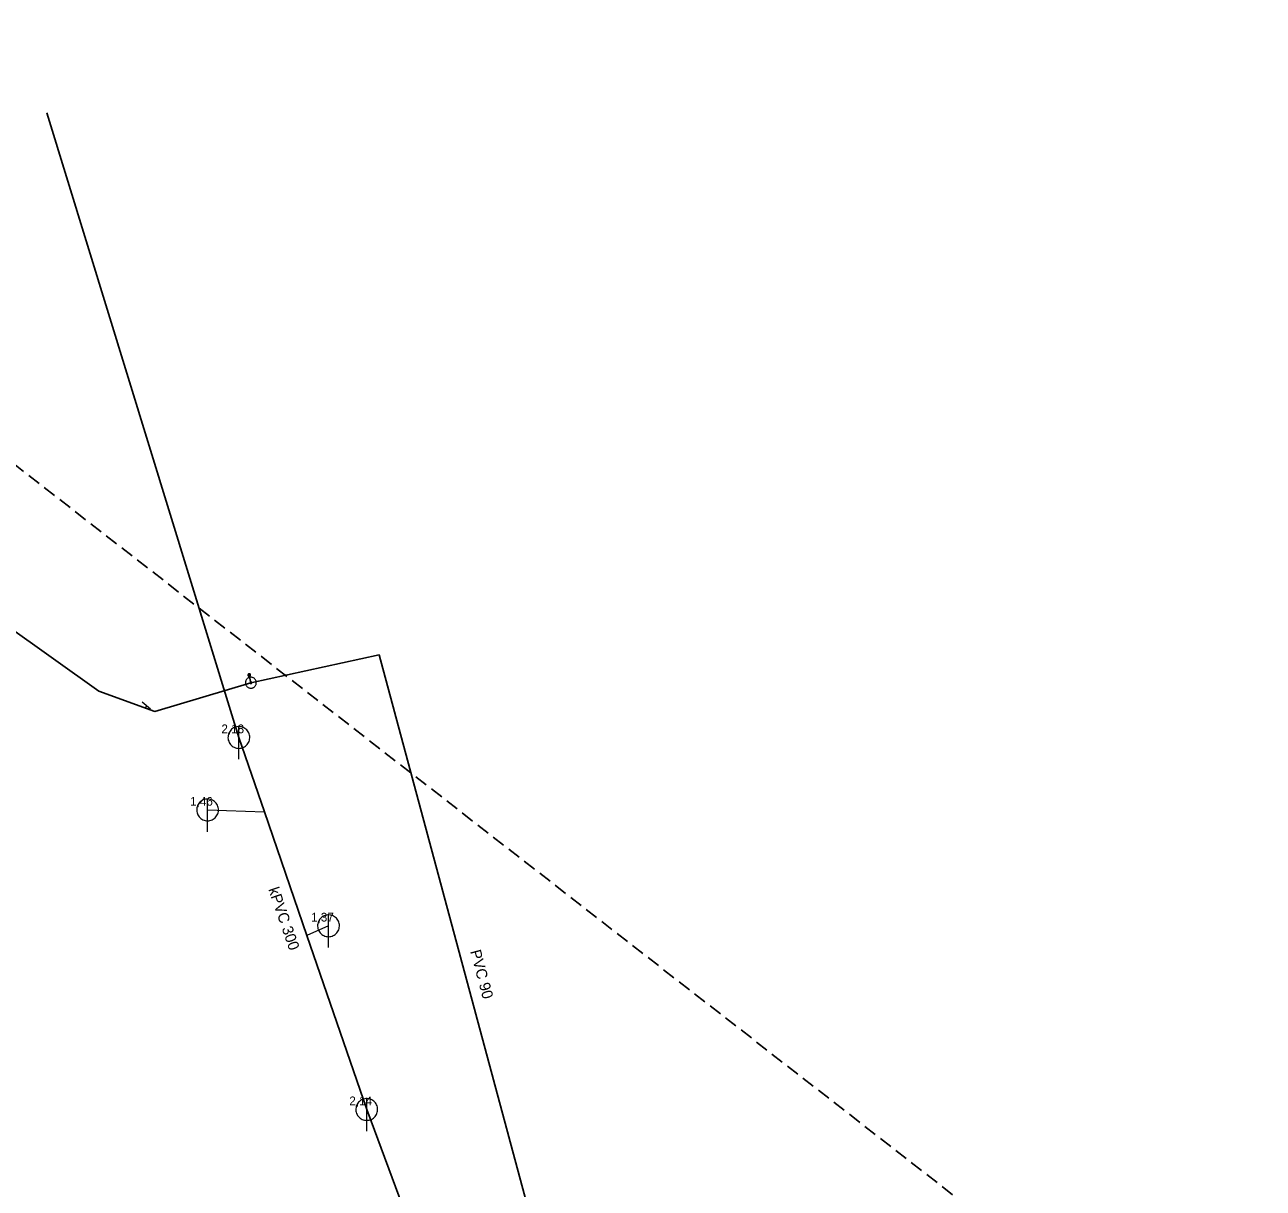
# Model space of a CAD drawing. Extents: x -683466 to -682479, y -996772 to -995963.
# Drawn here: x -682772.5 to -682658.8, y -996467.6 to -996360.9 of the extents above; entities that cross this region are included whole.
import ezdxf

# ---------------------------------------------------------------- set-up
doc = ezdxf.new("R2010")
doc.units = 0
doc.header["$LTSCALE"] = 0.4
doc.linetypes.add('MEDIUM_DASHED', pattern=[4.5, 3, -1.5])
doc.layers.add('1', color=7, linetype='Continuous')
for name, color, linetype, lineweight in [('11', 7, 'Continuous', 13), ('14', 7, 'Continuous', 25), ('17', 7, 'Continuous', 25), ('22', 7, 'Continuous', 13), ('34', 7, 'Continuous', 13), ('47', 7, 'Continuous', 13), ('63', 7, 'MEDIUM_DASHED', 25), ('9', 7, 'Continuous', 13)]:
    doc.layers.add(name, color=color, linetype=linetype, lineweight=lineweight)

msp = doc.modelspace()

# ---------------------------------------------------------------- linework, layer by layer
at = {"layer": '11'}
for p, q in [((-682755.69, -996432.879), (-682750.48, -996433.039)), ((-682744.596, -996443.508), (-682746.572, -996444.406))]:
    msp.add_line(p, q, dxfattribs=at)
at = {"layer": '14', "lineweight": 13}
msp.add_line((-682761.363, -996423.537), (-682761.309, -996423.309), dxfattribs=at)
at = {"layer": '14'}
msp.add_line((-682741.09, -996460.359), (-682726.26, -996500.32), dxfattribs=at)
for points in [[(-682770.44, -996368.94), (-682753.583, -996423.745), (-682752.82, -996426.23)], [(-682752.82, -996426.23), (-682750.48, -996433.039), (-682746.572, -996444.406), (-682741.09, -996460.359)]]:
    msp.add_lwpolyline(points, dxfattribs=at)
at = {"layer": '17'}
msp.add_line((-682751.718, -996421.207), (-682751.87, -996420.51), dxfattribs=at)
for points in [[(-682751.718, -996421.207), (-682760.52, -996423.84), (-682765.68, -996421.989), (-682774.19, -996415.899), (-682776.629, -996417.879), (-682778.359, -996420.489), (-682785.68, -996422.469), (-682789.414, -996420.431), (-682805.899, -996413.609)], [(-682688.579, -996470.29), (-682723.62, -996479.34), (-682739.951, -996418.663), (-682751.718, -996421.207)]]:
    msp.add_lwpolyline(points, dxfattribs=at)
at = {"layer": '22'}
for p, q in [((-682752.82, -996428.23), (-682752.819, -996425.23)), ((-682755.69, -996434.879), (-682755.689, -996431.879)), ((-682744.596, -996445.508), (-682744.595, -996442.508)), ((-682741.09, -996462.359), (-682741.089, -996459.359))]:
    msp.add_line(p, q, dxfattribs=at)
for points in [[(-682751.82, -996426.23), (-682751.825, -996426.121), (-682751.843, -996426.013), (-682751.873, -996425.907), (-682751.913, -996425.806), (-682751.965, -996425.709), (-682752.027, -996425.619), (-682752.099, -996425.536), (-682752.179, -996425.462), (-682752.267, -996425.396), (-682752.361, -996425.341), (-682752.461, -996425.296), (-682752.566, -996425.263), (-682752.673, -996425.241), (-682752.782, -996425.231), (-682752.892, -996425.233), (-682753, -996425.247), (-682753.107, -996425.272), (-682753.21, -996425.309), (-682753.308, -996425.358), (-682753.4, -996425.416), (-682753.486, -996425.485), (-682753.563, -996425.562), (-682753.632, -996425.648), (-682753.691, -996425.74), (-682753.739, -996425.838), (-682753.776, -996425.941), (-682753.802, -996426.048), (-682753.816, -996426.156), (-682753.819, -996426.266), (-682753.809, -996426.375), (-682753.788, -996426.482), (-682753.754, -996426.586), (-682753.71, -996426.686), (-682753.655, -996426.781), (-682753.589, -996426.869), (-682753.515, -996426.949), (-682753.432, -996427.021), (-682753.342, -996427.083), (-682753.246, -996427.135), (-682753.144, -996427.176), (-682753.039, -996427.206), (-682752.931, -996427.224), (-682752.821, -996427.23), (-682752.712, -996427.224), (-682752.604, -996427.206), (-682752.499, -996427.177), (-682752.397, -996427.136), (-682752.3, -996427.084), (-682752.21, -996427.022), (-682752.127, -996426.951), (-682752.052, -996426.871), (-682751.987, -996426.783), (-682751.931, -996426.689), (-682751.887, -996426.589), (-682751.853, -996426.485), (-682751.831, -996426.377), (-682751.821, -996426.268)], [(-682754.69, -996432.879), (-682754.695, -996432.77), (-682754.713, -996432.662), (-682754.743, -996432.556), (-682754.783, -996432.455), (-682754.835, -996432.358), (-682754.897, -996432.268), (-682754.969, -996432.185), (-682755.049, -996432.111), (-682755.137, -996432.045), (-682755.231, -996431.99), (-682755.331, -996431.945), (-682755.436, -996431.912), (-682755.543, -996431.89), (-682755.652, -996431.88), (-682755.762, -996431.882), (-682755.87, -996431.896), (-682755.977, -996431.921), (-682756.08, -996431.958), (-682756.178, -996432.007), (-682756.27, -996432.065), (-682756.356, -996432.134), (-682756.433, -996432.211), (-682756.502, -996432.297), (-682756.561, -996432.389), (-682756.609, -996432.487), (-682756.646, -996432.59), (-682756.672, -996432.697), (-682756.686, -996432.805), (-682756.689, -996432.915), (-682756.679, -996433.024), (-682756.658, -996433.131), (-682756.624, -996433.235), (-682756.58, -996433.335), (-682756.525, -996433.43), (-682756.459, -996433.518), (-682756.385, -996433.598), (-682756.302, -996433.67), (-682756.212, -996433.732), (-682756.116, -996433.784), (-682756.014, -996433.825), (-682755.909, -996433.855), (-682755.801, -996433.873), (-682755.691, -996433.879), (-682755.582, -996433.873), (-682755.474, -996433.855), (-682755.369, -996433.826), (-682755.267, -996433.785), (-682755.17, -996433.733), (-682755.08, -996433.671), (-682754.997, -996433.6), (-682754.922, -996433.52), (-682754.857, -996433.432), (-682754.801, -996433.338), (-682754.757, -996433.238), (-682754.723, -996433.134), (-682754.701, -996433.026), (-682754.691, -996432.917)], [(-682743.596, -996443.508), (-682743.601, -996443.399), (-682743.619, -996443.291), (-682743.649, -996443.185), (-682743.689, -996443.084), (-682743.741, -996442.987), (-682743.803, -996442.897), (-682743.875, -996442.814), (-682743.955, -996442.74), (-682744.043, -996442.674), (-682744.137, -996442.619), (-682744.237, -996442.574), (-682744.342, -996442.541), (-682744.449, -996442.519), (-682744.558, -996442.509), (-682744.668, -996442.511), (-682744.776, -996442.525), (-682744.883, -996442.55), (-682744.986, -996442.587), (-682745.084, -996442.636), (-682745.176, -996442.694), (-682745.262, -996442.763), (-682745.339, -996442.84), (-682745.408, -996442.926), (-682745.467, -996443.018), (-682745.515, -996443.116), (-682745.552, -996443.219), (-682745.578, -996443.326), (-682745.592, -996443.434), (-682745.595, -996443.544), (-682745.585, -996443.653), (-682745.564, -996443.76), (-682745.53, -996443.864), (-682745.486, -996443.964), (-682745.431, -996444.059), (-682745.365, -996444.147), (-682745.291, -996444.227), (-682745.208, -996444.299), (-682745.118, -996444.361), (-682745.022, -996444.413), (-682744.92, -996444.454), (-682744.815, -996444.484), (-682744.707, -996444.502), (-682744.597, -996444.508), (-682744.488, -996444.502), (-682744.38, -996444.484), (-682744.275, -996444.455), (-682744.173, -996444.414), (-682744.076, -996444.362), (-682743.986, -996444.3), (-682743.903, -996444.229), (-682743.828, -996444.149), (-682743.763, -996444.061), (-682743.707, -996443.967), (-682743.663, -996443.867), (-682743.629, -996443.763), (-682743.607, -996443.655), (-682743.597, -996443.546)], [(-682740.09, -996460.359), (-682740.095, -996460.25), (-682740.113, -996460.142), (-682740.143, -996460.036), (-682740.183, -996459.935), (-682740.235, -996459.838), (-682740.297, -996459.748), (-682740.369, -996459.665), (-682740.449, -996459.591), (-682740.537, -996459.525), (-682740.631, -996459.47), (-682740.731, -996459.425), (-682740.836, -996459.392), (-682740.943, -996459.37), (-682741.052, -996459.36), (-682741.162, -996459.362), (-682741.27, -996459.376), (-682741.377, -996459.401), (-682741.48, -996459.438), (-682741.578, -996459.487), (-682741.67, -996459.545), (-682741.756, -996459.614), (-682741.833, -996459.691), (-682741.902, -996459.777), (-682741.961, -996459.869), (-682742.009, -996459.967), (-682742.046, -996460.07), (-682742.072, -996460.177), (-682742.086, -996460.285), (-682742.089, -996460.395), (-682742.079, -996460.504), (-682742.058, -996460.611), (-682742.024, -996460.715), (-682741.98, -996460.815), (-682741.925, -996460.91), (-682741.859, -996460.998), (-682741.785, -996461.078), (-682741.702, -996461.15), (-682741.612, -996461.212), (-682741.516, -996461.264), (-682741.414, -996461.305), (-682741.309, -996461.335), (-682741.201, -996461.353), (-682741.091, -996461.359), (-682740.982, -996461.353), (-682740.874, -996461.335), (-682740.769, -996461.306), (-682740.667, -996461.265), (-682740.57, -996461.213), (-682740.48, -996461.151), (-682740.397, -996461.08), (-682740.322, -996461), (-682740.257, -996460.912), (-682740.201, -996460.818), (-682740.157, -996460.718), (-682740.123, -996460.614), (-682740.101, -996460.506), (-682740.091, -996460.397)]]:
    msp.add_lwpolyline(points, close=True, dxfattribs=at)
at = {"layer": '34'}
msp.add_line((-682760.926, -996423.631), (-682761.69, -996422.985), dxfattribs=at)
at = {"layer": '47'}
for points in [[(-682751.218, -996421.207), (-682751.221, -996421.155), (-682751.229, -996421.103), (-682751.243, -996421.053), (-682751.261, -996421.004), (-682751.285, -996420.957), (-682751.314, -996420.913), (-682751.347, -996420.873), (-682751.384, -996420.836), (-682751.424, -996420.803), (-682751.468, -996420.774), (-682751.515, -996420.75), (-682751.564, -996420.732), (-682751.614, -996420.718), (-682751.666, -996420.71), (-682751.718, -996420.707), (-682751.77, -996420.71), (-682751.822, -996420.718), (-682751.873, -996420.732), (-682751.921, -996420.75), (-682751.968, -996420.774), (-682752.012, -996420.803), (-682752.053, -996420.836), (-682752.09, -996420.873), (-682752.123, -996420.913), (-682752.151, -996420.957), (-682752.175, -996421.004), (-682752.194, -996421.053), (-682752.206, -996421.103), (-682752.215, -996421.155), (-682752.218, -996421.207), (-682752.215, -996421.259), (-682752.206, -996421.311), (-682752.194, -996421.362), (-682752.175, -996421.41), (-682752.151, -996421.457), (-682752.123, -996421.501), (-682752.09, -996421.542), (-682752.053, -996421.579), (-682752.012, -996421.612), (-682751.968, -996421.64), (-682751.921, -996421.664), (-682751.873, -996421.683), (-682751.822, -996421.696), (-682751.77, -996421.704), (-682751.718, -996421.707), (-682751.666, -996421.704), (-682751.614, -996421.696), (-682751.564, -996421.683), (-682751.515, -996421.664), (-682751.468, -996421.64), (-682751.424, -996421.612), (-682751.384, -996421.579), (-682751.347, -996421.542), (-682751.314, -996421.501), (-682751.285, -996421.457), (-682751.261, -996421.41), (-682751.243, -996421.362), (-682751.229, -996421.311), (-682751.221, -996421.259)], [(-682751.636, -996421.207), (-682751.636, -996421.198), (-682751.638, -996421.19), (-682751.64, -996421.182), (-682751.643, -996421.174), (-682751.647, -996421.166), (-682751.652, -996421.159), (-682751.657, -996421.152), (-682751.663, -996421.146), (-682751.67, -996421.141), (-682751.677, -996421.136), (-682751.684, -996421.132), (-682751.693, -996421.129), (-682751.701, -996421.127), (-682751.709, -996421.125), (-682751.718, -996421.125), (-682751.727, -996421.125), (-682751.735, -996421.127), (-682751.743, -996421.129), (-682751.751, -996421.132), (-682751.759, -996421.136), (-682751.766, -996421.141), (-682751.773, -996421.146), (-682751.779, -996421.152), (-682751.785, -996421.159), (-682751.789, -996421.166), (-682751.793, -996421.174), (-682751.796, -996421.182), (-682751.798, -996421.19), (-682751.8, -996421.198), (-682751.8, -996421.207), (-682751.8, -996421.216), (-682751.798, -996421.224), (-682751.796, -996421.232), (-682751.793, -996421.24), (-682751.789, -996421.248), (-682751.785, -996421.255), (-682751.779, -996421.262), (-682751.773, -996421.268), (-682751.766, -996421.274), (-682751.759, -996421.278), (-682751.751, -996421.282), (-682751.743, -996421.285), (-682751.735, -996421.287), (-682751.727, -996421.289), (-682751.718, -996421.289), (-682751.709, -996421.289), (-682751.701, -996421.287), (-682751.693, -996421.285), (-682751.684, -996421.282), (-682751.677, -996421.278), (-682751.67, -996421.274), (-682751.663, -996421.268), (-682751.657, -996421.262), (-682751.652, -996421.255), (-682751.647, -996421.248), (-682751.643, -996421.24), (-682751.64, -996421.232), (-682751.638, -996421.224), (-682751.636, -996421.216)]]:
    msp.add_lwpolyline(points, close=True, dxfattribs=at)
at = {"layer": '63'}
msp.add_lwpolyline([(-683425.281, -996021.839), (-683425.281, -996016.256), (-683425.281, -996016.256), (-683335.962, -995963.223), (-683335.962, -995963.223), (-682479.059, -996630.324), (-682479.059, -996630.324), (-682551.631, -996711.269), (-682551.631, -996711.269), (-683416.907, -996083.246), (-683416.907, -996083.246)], close=True, dxfattribs=at)
at = {"layer": '9'}
for points in [[(-682751.996, -996420.51), (-682751.996, -996420.523), (-682751.994, -996420.536), (-682751.991, -996420.549), (-682751.986, -996420.561), (-682751.98, -996420.573), (-682751.973, -996420.584), (-682751.965, -996420.594), (-682751.955, -996420.604), (-682751.945, -996420.612), (-682751.934, -996420.619), (-682751.922, -996420.625), (-682751.91, -996420.63), (-682751.897, -996420.633), (-682751.884, -996420.635), (-682751.871, -996420.637), (-682751.858, -996420.636), (-682751.845, -996420.634), (-682751.832, -996420.631), (-682751.82, -996420.626), (-682751.808, -996420.62), (-682751.797, -996420.613), (-682751.787, -996420.605), (-682751.777, -996420.595), (-682751.769, -996420.585), (-682751.762, -996420.574), (-682751.756, -996420.562), (-682751.751, -996420.55), (-682751.748, -996420.537), (-682751.746, -996420.524), (-682751.744, -996420.511), (-682751.745, -996420.498), (-682751.747, -996420.485), (-682751.75, -996420.472), (-682751.755, -996420.46), (-682751.761, -996420.448), (-682751.768, -996420.437), (-682751.776, -996420.427), (-682751.786, -996420.417), (-682751.796, -996420.409), (-682751.807, -996420.402), (-682751.819, -996420.396), (-682751.831, -996420.391), (-682751.844, -996420.388), (-682751.857, -996420.386), (-682751.87, -996420.385), (-682751.883, -996420.385), (-682751.896, -996420.387), (-682751.909, -996420.39), (-682751.921, -996420.395), (-682751.933, -996420.401), (-682751.944, -996420.408), (-682751.954, -996420.416), (-682751.964, -996420.426), (-682751.972, -996420.436), (-682751.979, -996420.447), (-682751.985, -996420.459), (-682751.99, -996420.471), (-682751.993, -996420.484), (-682751.995, -996420.497)], [(-682751.976, -996420.51), (-682751.977, -996420.521), (-682751.975, -996420.532), (-682751.972, -996420.543), (-682751.968, -996420.553), (-682751.963, -996420.563), (-682751.957, -996420.572), (-682751.95, -996420.581), (-682751.942, -996420.589), (-682751.933, -996420.596), (-682751.924, -996420.602), (-682751.914, -996420.607), (-682751.904, -996420.611), (-682751.893, -996420.614), (-682751.882, -996420.617), (-682751.871, -996420.617), (-682751.86, -996420.617), (-682751.849, -996420.615), (-682751.838, -996420.612), (-682751.828, -996420.608), (-682751.818, -996420.603), (-682751.809, -996420.597), (-682751.8, -996420.59), (-682751.792, -996420.582), (-682751.785, -996420.573), (-682751.779, -996420.564), (-682751.774, -996420.554), (-682751.77, -996420.544), (-682751.767, -996420.533), (-682751.765, -996420.522), (-682751.764, -996420.511), (-682751.764, -996420.5), (-682751.766, -996420.489), (-682751.769, -996420.478), (-682751.773, -996420.468), (-682751.778, -996420.458), (-682751.784, -996420.449), (-682751.791, -996420.44), (-682751.799, -996420.432), (-682751.808, -996420.425), (-682751.817, -996420.419), (-682751.827, -996420.414), (-682751.837, -996420.41), (-682751.848, -996420.407), (-682751.858, -996420.405), (-682751.87, -996420.405), (-682751.881, -996420.404), (-682751.892, -996420.406), (-682751.903, -996420.409), (-682751.913, -996420.413), (-682751.923, -996420.418), (-682751.932, -996420.424), (-682751.941, -996420.431), (-682751.949, -996420.439), (-682751.956, -996420.448), (-682751.962, -996420.457), (-682751.967, -996420.467), (-682751.971, -996420.477), (-682751.974, -996420.488), (-682751.976, -996420.499)], [(-682751.957, -996420.51), (-682751.957, -996420.519), (-682751.956, -996420.528), (-682751.953, -996420.537), (-682751.95, -996420.545), (-682751.946, -996420.553), (-682751.941, -996420.561), (-682751.934, -996420.568), (-682751.929, -996420.574), (-682751.922, -996420.58), (-682751.914, -996420.585), (-682751.906, -996420.589), (-682751.898, -996420.592), (-682751.889, -996420.595), (-682751.88, -996420.596), (-682751.871, -996420.598), (-682751.862, -996420.597), (-682751.853, -996420.596), (-682751.844, -996420.593), (-682751.836, -996420.59), (-682751.828, -996420.586), (-682751.82, -996420.581), (-682751.813, -996420.575), (-682751.807, -996420.569), (-682751.801, -996420.562), (-682751.796, -996420.554), (-682751.792, -996420.546), (-682751.789, -996420.538), (-682751.786, -996420.529), (-682751.785, -996420.52), (-682751.782, -996420.511), (-682751.784, -996420.502), (-682751.785, -996420.493), (-682751.788, -996420.484), (-682751.791, -996420.476), (-682751.795, -996420.468), (-682751.8, -996420.46), (-682751.806, -996420.453), (-682751.812, -996420.447), (-682751.819, -996420.441), (-682751.827, -996420.436), (-682751.835, -996420.432), (-682751.843, -996420.429), (-682751.852, -996420.426), (-682751.861, -996420.425), (-682751.87, -996420.424), (-682751.879, -996420.424), (-682751.888, -996420.425), (-682751.897, -996420.428), (-682751.905, -996420.431), (-682751.913, -996420.435), (-682751.921, -996420.44), (-682751.928, -996420.446), (-682751.934, -996420.452), (-682751.94, -996420.459), (-682751.945, -996420.467), (-682751.949, -996420.475), (-682751.952, -996420.483), (-682751.955, -996420.492), (-682751.956, -996420.501)], [(-682751.937, -996420.51), (-682751.937, -996420.517), (-682751.936, -996420.524), (-682751.934, -996420.531), (-682751.932, -996420.537), (-682751.929, -996420.543), (-682751.925, -996420.549), (-682751.921, -996420.555), (-682751.916, -996420.56), (-682751.91, -996420.564), (-682751.904, -996420.568), (-682751.898, -996420.571), (-682751.892, -996420.574), (-682751.885, -996420.575), (-682751.878, -996420.578), (-682751.871, -996420.578), (-682751.864, -996420.578), (-682751.857, -996420.576), (-682751.85, -996420.575), (-682751.844, -996420.572), (-682751.837, -996420.569), (-682751.832, -996420.565), (-682751.826, -996420.561), (-682751.821, -996420.556), (-682751.817, -996420.55), (-682751.813, -996420.544), (-682751.809, -996420.538), (-682751.807, -996420.532), (-682751.805, -996420.525), (-682751.804, -996420.518), (-682751.803, -996420.511), (-682751.803, -996420.504), (-682751.804, -996420.497), (-682751.806, -996420.49), (-682751.809, -996420.484), (-682751.812, -996420.477), (-682751.816, -996420.472), (-682751.82, -996420.466), (-682751.825, -996420.461), (-682751.831, -996420.457), (-682751.836, -996420.453), (-682751.843, -996420.45), (-682751.849, -996420.447), (-682751.856, -996420.445), (-682751.863, -996420.444), (-682751.87, -996420.444), (-682751.877, -996420.444), (-682751.884, -996420.444), (-682751.891, -996420.446), (-682751.897, -996420.449), (-682751.903, -996420.452), (-682751.909, -996420.456), (-682751.915, -996420.46), (-682751.92, -996420.465), (-682751.924, -996420.471), (-682751.928, -996420.476), (-682751.931, -996420.483), (-682751.934, -996420.489), (-682751.934, -996420.496), (-682751.937, -996420.503)], [(-682751.917, -996420.51), (-682751.917, -996420.515), (-682751.917, -996420.52), (-682751.916, -996420.525), (-682751.914, -996420.529), (-682751.912, -996420.534), (-682751.909, -996420.538), (-682751.906, -996420.541), (-682751.902, -996420.545), (-682751.899, -996420.548), (-682751.895, -996420.551), (-682751.89, -996420.553), (-682751.886, -996420.555), (-682751.881, -996420.556), (-682751.876, -996420.558), (-682751.871, -996420.558), (-682751.866, -996420.558), (-682751.861, -996420.557), (-682751.856, -996420.556), (-682751.852, -996420.554), (-682751.847, -996420.552), (-682751.843, -996420.549), (-682751.839, -996420.546), (-682751.836, -996420.542), (-682751.833, -996420.539), (-682751.83, -996420.535), (-682751.828, -996420.53), (-682751.826, -996420.526), (-682751.825, -996420.521), (-682751.824, -996420.516), (-682751.823, -996420.511), (-682751.823, -996420.506), (-682751.824, -996420.501), (-682751.825, -996420.496), (-682751.827, -996420.492), (-682751.829, -996420.487), (-682751.832, -996420.483), (-682751.835, -996420.479), (-682751.838, -996420.476), (-682751.842, -996420.473), (-682751.846, -996420.47), (-682751.851, -996420.468), (-682751.855, -996420.466), (-682751.86, -996420.465), (-682751.865, -996420.464), (-682751.87, -996420.464), (-682751.875, -996420.464), (-682751.88, -996420.465), (-682751.885, -996420.465), (-682751.889, -996420.467), (-682751.894, -996420.469), (-682751.898, -996420.472), (-682751.901, -996420.475), (-682751.905, -996420.478), (-682751.907, -996420.482), (-682751.911, -996420.486), (-682751.913, -996420.491), (-682751.915, -996420.495), (-682751.916, -996420.5), (-682751.917, -996420.505)], [(-682751.897, -996420.51), (-682751.897, -996420.513), (-682751.898, -996420.516), (-682751.897, -996420.518), (-682751.896, -996420.521), (-682751.895, -996420.524), (-682751.893, -996420.526), (-682751.891, -996420.528), (-682751.889, -996420.53), (-682751.887, -996420.532), (-682751.885, -996420.534), (-682751.882, -996420.536), (-682751.879, -996420.537), (-682751.877, -996420.537), (-682751.874, -996420.538), (-682751.871, -996420.538), (-682751.868, -996420.538), (-682751.865, -996420.538), (-682751.862, -996420.537), (-682751.86, -996420.536), (-682751.857, -996420.535), (-682751.855, -996420.533), (-682751.852, -996420.531), (-682751.85, -996420.529), (-682751.849, -996420.527), (-682751.847, -996420.525), (-682751.846, -996420.522), (-682751.844, -996420.519), (-682751.844, -996420.517), (-682751.843, -996420.514), (-682751.842, -996420.511), (-682751.843, -996420.508), (-682751.843, -996420.505), (-682751.844, -996420.502), (-682751.845, -996420.5), (-682751.846, -996420.497), (-682751.848, -996420.495), (-682751.849, -996420.492), (-682751.851, -996420.49), (-682751.854, -996420.489), (-682751.856, -996420.487), (-682751.858, -996420.486), (-682751.861, -996420.485), (-682751.864, -996420.484), (-682751.867, -996420.484), (-682751.87, -996420.483), (-682751.873, -996420.484), (-682751.876, -996420.483), (-682751.878, -996420.485), (-682751.881, -996420.485), (-682751.884, -996420.486), (-682751.886, -996420.488), (-682751.888, -996420.489), (-682751.89, -996420.491), (-682751.892, -996420.494), (-682751.894, -996420.496), (-682751.895, -996420.499), (-682751.896, -996420.501), (-682751.897, -996420.504), (-682751.897, -996420.507)], [(-682751.878, -996420.51), (-682751.878, -996420.512), (-682751.878, -996420.512), (-682751.877, -996420.512), (-682751.877, -996420.514), (-682751.878, -996420.515), (-682751.876, -996420.515), (-682751.876, -996420.515), (-682751.876, -996420.517), (-682751.876, -996420.517), (-682751.875, -996420.518), (-682751.873, -996420.518), (-682751.873, -996420.518), (-682751.873, -996420.519), (-682751.871, -996420.519), (-682751.871, -996420.519), (-682751.87, -996420.519), (-682751.869, -996420.519), (-682751.869, -996420.518), (-682751.868, -996420.518), (-682751.866, -996420.518), (-682751.866, -996420.517), (-682751.866, -996420.517), (-682751.865, -996420.516), (-682751.865, -996420.516), (-682751.863, -996420.515), (-682751.863, -996420.514), (-682751.862, -996420.513), (-682751.862, -996420.513), (-682751.862, -996420.512), (-682751.862, -996420.511), (-682751.862, -996420.51), (-682751.862, -996420.509), (-682751.862, -996420.509), (-682751.863, -996420.508), (-682751.863, -996420.507), (-682751.864, -996420.506), (-682751.864, -996420.506), (-682751.865, -996420.505), (-682751.865, -996420.505), (-682751.866, -996420.504), (-682751.867, -996420.504), (-682751.868, -996420.503), (-682751.868, -996420.503), (-682751.869, -996420.503), (-682751.87, -996420.503), (-682751.871, -996420.503), (-682751.872, -996420.503), (-682751.872, -996420.503), (-682751.873, -996420.504), (-682751.874, -996420.503), (-682751.875, -996420.505), (-682751.875, -996420.505), (-682751.876, -996420.505), (-682751.876, -996420.505), (-682751.877, -996420.507), (-682751.877, -996420.508), (-682751.877, -996420.509), (-682751.878, -996420.509), (-682751.878, -996420.51)]]:
    msp.add_lwpolyline(points, close=True, dxfattribs=at)

# ---------------------------------------------------------------- texts
at = {"layer": '1'}
for s, p in [('2,18', (-682754.42, -996425.841)), ('1,46', (-682757.289, -996432.491)), ('1,37', (-682746.196, -996443.119)), ('2,14', (-682742.689, -996459.971))]:
    msp.add_text(s, height=0.8, dxfattribs=at).set_placement(p)
for s, rotation, p in [('kPVC 300', 289, (-682750.131, -996440.156)), ('PVC 90', 285, (-682731.613, -996445.848))]:
    msp.add_text(s, height=1, rotation=rotation, dxfattribs=at).set_placement(p)

doc.saveas('drawing.dxf')
